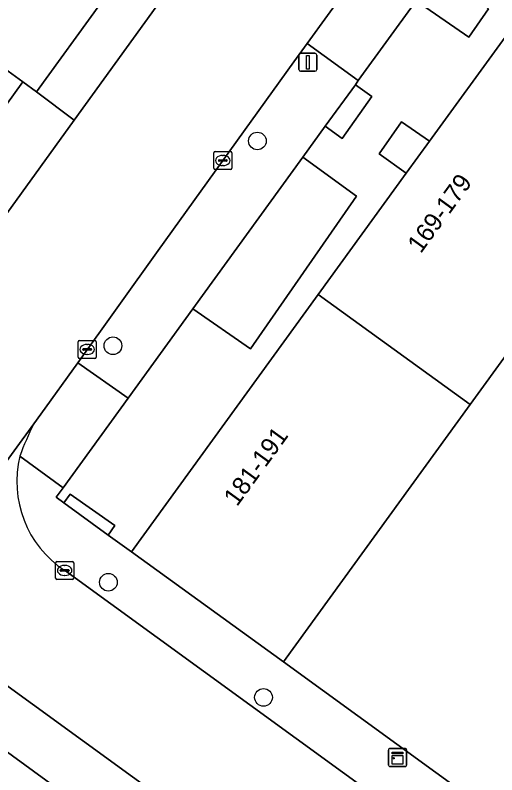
# Model space of a CAD drawing. Extents: x 159674 to 160531, y 382172 to 382904.
# Drawn here: x 160192.42 to 160219.05, y 382438.2 to 382480.25 of the extents above; entities that cross this region are included whole.
import ezdxf

# ---------------------------------------------------------------- set-up
doc = ezdxf.new("R2010")
doc.units = 0
for name, color, linetype in [('IMGEO_Boom', 7, 'Continuous'), ('IMGEO_Erf', 7, 'Continuous'), ('IMGEO_Groenvoorziening', 7, 'Continuous'), ('IMGEO_Kast', 7, 'Continuous'), ('IMGEO_Kolk', 7, 'Continuous'), ('IMGEO_Lichtmast', 7, 'Continuous'), ('IMGEO_Pand', 7, 'Continuous'), ('IMGEO_Pand_nummerreeks', 7, 'Continuous'), ('IMGEO_Rijbaan_lokaal_gesloten', 7, 'Continuous'), ('IMGEO_Rijbaan_lokaal_open', 7, 'Continuous'), ('IMGEO_Voetpad_open', 7, 'Continuous')]:
    doc.layers.add(name, color=color, linetype=linetype)

msp = doc.modelspace()

# ---------------------------------------------------------------- linework, layer by layer
at = {"layer": 'IMGEO_Boom'}
for centre in [(160205.813, 382473.283), (160197.829, 382461.949), (160197.574, 382448.859), (160206.154, 382442.486)]:
    msp.add_circle(centre, 0.489, dxfattribs=at)
at = {"layer": 'IMGEO_Erf'}
msp.add_lwpolyline([(160182.094, 382492.77), (160177.116, 382496.389), (160172.149, 382500), (160165.851, 382491.086), (160168.791, 382488.896), (160171.386, 382492.38), (160173.197, 382491.031), (160175.695, 382489.17), (160173.177, 382485.697), (160175.768, 382483.874), (160179.323, 382488.647), (160182.164, 382486.531), (160181.035, 382485.016), (160182.848, 382483.665), (160184.767, 382482.236), (160182.34, 382478.979), (160182.963, 382478.515), (160185.543, 382476.768), (160187.968, 382480.105), (160192.854, 382476.554), (160193.609, 382475.995), (160197.153, 382480.914)], dxfattribs=at)
at = {"layer": 'IMGEO_Groenvoorziening'}
msp.add_lwpolyline([(160254.885, 382500), (160239.266, 382511.108), (160237.217, 382512.565), (160235.158, 382509.653), (160239.464, 382506.53), (160240.092, 382507.396), (160248.493, 382501.304), (160247.547, 382500), (160238.256, 382487.19), (160227.923, 382472.943), (160217.589, 382458.696), (160207.256, 382444.449), (160248.967, 382414.122)], dxfattribs=at)
for points in [[(160215.757, 382482.642), (160214.787, 382481.302), (160214.604, 382481.05), (160217.516, 382479.035), (160218.591, 382480.589)], [(160211.235, 382476.399), (160209.566, 382474.095), (160210.502, 382473.418), (160212.151, 382475.752)], [(160215.333, 382473.267), (160213.776, 382474.343), (160212.558, 382472.581), (160214.05, 382471.498)], [(160208.327, 382472.386), (160202.241, 382463.985), (160205.436, 382461.77), (160211.301, 382470.232)], [(160195.105, 382453.261), (160197.564, 382451.474), (160197.933, 382451.998), (160195.455, 382453.742)]]:
    msp.add_lwpolyline(points, close=True, dxfattribs=at)
at = {"layer": 'IMGEO_Kast'}
for p, q in [((160213.143, 382439.656), (160213.984, 382439.656)), ((160213.984, 382439.656), (160213.143, 382439.656)), ((160213.068, 382438.731), (160213.068, 382439.572)), ((160213.068, 382439.572), (160213.068, 382438.731)), ((160214.068, 382439.581), (160214.068, 382438.74)), ((160214.068, 382438.74), (160214.068, 382439.581)), ((160213.993, 382438.656), (160213.152, 382438.656)), ((160213.152, 382438.656), (160213.993, 382438.656))]:
    msp.add_line(p, q, dxfattribs=at)
for points in [[(160213.263, 382439.446), (160213.863, 382439.446), (160213.863, 382439.361), (160213.263, 382439.361), (160213.263, 382439.446)], [(160213.263, 382439.271), (160213.863, 382439.271), (160213.863, 382438.782), (160213.263, 382438.782), (160213.263, 382439.271)]]:
    msp.add_lwpolyline(points, dxfattribs=at)
msp.add_circle((160213.347, 382439.12), 0.0377, dxfattribs=at)
for centre, start, end in [((160213.146, 382439.578), 92.4484, 184.2845), ((160213.146, 382439.578), 92.4484, 184.2845), ((160213.99, 382439.578), 2.4484, 94.2845), ((160213.99, 382439.578), 2.4484, 94.2845), ((160213.146, 382438.734), 182.4484, 274.2845), ((160213.146, 382438.734), 182.4484, 274.2845), ((160213.99, 382438.734), 272.4484, 4.2845), ((160213.99, 382438.734), 272.4484, 4.2845)]:
    msp.add_arc(centre, 0.0779, start, end, dxfattribs=at)
at = {"layer": 'IMGEO_Kolk'}
for p, q in [((160203.404, 382471.776), (160203.404, 382472.628)), ((160203.479, 382472.702), (160204.331, 382472.702)), ((160203.892, 382472.482), (160203.917, 382472.482)), ((160204.405, 382472.628), (160204.405, 382471.776)), ((160203.663, 382472.196), (160203.663, 382472.208)), ((160204.101, 382472.159), (160203.703, 382472.159)), ((160203.706, 382472.245), (160204.104, 382472.245)), ((160204.147, 382472.208), (160204.147, 382472.196)), ((160204.331, 382471.702), (160203.479, 382471.702)), ((160203.915, 382471.922), (160203.89, 382471.922)), ((160195.905, 382461.32), (160195.905, 382462.172)), ((160195.98, 382462.246), (160196.832, 382462.246)), ((160196.393, 382462.026), (160196.418, 382462.026)), ((160196.906, 382462.172), (160196.906, 382461.32)), ((160196.164, 382461.74), (160196.164, 382461.752)), ((160196.602, 382461.703), (160196.204, 382461.703)), ((160196.207, 382461.789), (160196.605, 382461.789)), ((160196.648, 382461.752), (160196.648, 382461.74)), ((160196.832, 382461.246), (160195.98, 382461.246)), ((160196.416, 382461.466), (160196.391, 382461.466)), ((160194.658, 382449.087), (160194.658, 382449.939)), ((160194.733, 382450.013), (160195.585, 382450.013)), ((160195.146, 382449.793), (160195.171, 382449.793)), ((160195.659, 382449.939), (160195.659, 382449.087)), ((160194.917, 382449.507), (160194.917, 382449.519)), ((160195.355, 382449.47), (160194.957, 382449.47)), ((160194.96, 382449.556), (160195.358, 382449.556)), ((160195.401, 382449.519), (160195.401, 382449.507)), ((160195.585, 382449.013), (160194.733, 382449.013)), ((160195.169, 382449.233), (160195.144, 382449.233))]:
    msp.add_line(p, q, dxfattribs=at)
for points in [[(160203.404, 382471.776), (160203.404, 382472.628)], [(160203.479, 382472.702), (160204.331, 382472.702)], [(160204.405, 382472.628), (160204.405, 382471.776)], [(160204.331, 382471.702), (160203.479, 382471.702)], [(160195.905, 382461.32), (160195.905, 382462.172)], [(160195.98, 382462.246), (160196.832, 382462.246)], [(160196.906, 382462.172), (160196.906, 382461.32)], [(160196.832, 382461.246), (160195.98, 382461.246)], [(160194.658, 382449.087), (160194.658, 382449.939)], [(160194.733, 382450.013), (160195.585, 382450.013)], [(160195.659, 382449.939), (160195.659, 382449.087)], [(160195.585, 382449.013), (160194.733, 382449.013)]]:
    msp.add_lwpolyline(points, dxfattribs=at)
for centre, radius, start, end in [((160203.481, 382472.626), 0.0765, 91.552, 178.448), ((160203.481, 382472.626), 0.0765, 91.552, 178.448), ((160204.329, 382472.626), 0.0765, 1.552, 88.448), ((160204.329, 382472.626), 0.0765, 1.552, 88.448), ((160203.703, 382472.205), 0.0403, 85.8775, 175.7526), ((160203.7, 382472.195), 0.0366, 178.938, 274.7102), ((160204.104, 382472.202), 0.043, 264.8664, 352.4533), ((160204.108, 382472.207), 0.0386, 1.7309, 96.639), ((160203.481, 382471.778), 0.0765, 181.552, 268.448), ((160203.481, 382471.778), 0.0765, 181.552, 268.448), ((160204.329, 382471.778), 0.0765, 271.552, 358.448), ((160204.329, 382471.778), 0.0765, 271.552, 358.448), ((160195.982, 382462.17), 0.0765, 91.552, 178.448), ((160195.982, 382462.17), 0.0765, 91.552, 178.448), ((160196.83, 382462.17), 0.0765, 1.552, 88.448), ((160196.83, 382462.17), 0.0765, 1.552, 88.448), ((160196.204, 382461.749), 0.0403, 85.8775, 175.7526), ((160196.201, 382461.739), 0.0366, 178.938, 274.7102), ((160196.605, 382461.746), 0.043, 264.8664, 352.4533), ((160196.609, 382461.751), 0.0386, 1.7309, 96.639), ((160195.982, 382461.322), 0.0765, 181.552, 268.448), ((160195.982, 382461.322), 0.0765, 181.552, 268.448), ((160196.83, 382461.322), 0.0765, 271.552, 358.448), ((160196.83, 382461.322), 0.0765, 271.552, 358.448), ((160194.735, 382449.937), 0.0765, 91.552, 178.448), ((160194.735, 382449.937), 0.0765, 91.552, 178.448), ((160195.583, 382449.937), 0.0765, 1.552, 88.448), ((160195.583, 382449.937), 0.0765, 1.552, 88.448), ((160194.957, 382449.516), 0.0403, 85.8775, 175.7526), ((160194.954, 382449.506), 0.0366, 178.938, 274.7102), ((160195.358, 382449.513), 0.043, 264.8664, 352.4533), ((160195.362, 382449.518), 0.0386, 1.7309, 96.639), ((160194.735, 382449.089), 0.0765, 181.552, 268.448), ((160194.735, 382449.089), 0.0765, 181.552, 268.448), ((160195.583, 382449.089), 0.0765, 271.552, 358.448), ((160195.583, 382449.089), 0.0765, 271.552, 358.448)]:
    msp.add_arc(centre, radius, start, end, dxfattribs=at)
for centre, major_axis, ratio, start_param, end_param in [((160203.891, 382472.202), (-0.387, 0.002), 0.722429, 4.712389, 7.853982), ((160203.916, 382472.202), (-0.39, 0.002), 0.717154, 1.570796, 4.712389), ((160196.392, 382461.746), (-0.387, 0.002), 0.722429, 4.712389, 7.853982), ((160196.417, 382461.746), (-0.39, 0.002), 0.717154, 1.570796, 4.712389), ((160195.145, 382449.513), (-0.387, 0.002), 0.722429, 4.712389, 7.853982), ((160195.17, 382449.513), (-0.39, 0.002), 0.717154, 1.570796, 4.712389)]:
    msp.add_ellipse(centre, major_axis=major_axis, ratio=ratio, start_param=start_param, end_param=end_param, dxfattribs=at)
at = {"layer": 'IMGEO_Lichtmast'}
for p, q in [((160208.108, 382477.241), (160208.108, 382478.041)), ((160208.108, 382478.041), (160208.108, 382477.241)), ((160208.208, 382478.141), (160208.998, 382478.141)), ((160208.998, 382478.141), (160208.208, 382478.141)), ((160209.098, 382478.041), (160209.098, 382477.241)), ((160209.098, 382477.241), (160209.098, 382478.041)), ((160208.998, 382477.141), (160208.208, 382477.141)), ((160208.208, 382477.141), (160208.998, 382477.141))]:
    msp.add_line(p, q, dxfattribs=at)
msp.add_lwpolyline([(160208.528, 382478.016), (160208.678, 382478.016), (160208.678, 382477.266), (160208.528, 382477.266), (160208.528, 382478.016)], dxfattribs=at)
for centre, start, end in [((160208.208, 382478.041), 90, 180), ((160208.208, 382478.041), 90, 180), ((160208.998, 382478.041), 0, 90), ((160208.998, 382478.041), 360, 90), ((160208.208, 382477.241), 180, 270), ((160208.208, 382477.241), 180, 270), ((160208.998, 382477.241), 270, 0), ((160208.998, 382477.241), 270, 0)]:
    msp.add_arc(centre, 0.1, start, end, dxfattribs=at)
at = {"layer": 'IMGEO_Pand'}
for points in [[(160192.854, 382476.554), (160187.968, 382480.105), (160185.543, 382476.768), (160190.429, 382473.217)], [(160227.923, 382472.943), (160219.517, 382479.034), (160215.333, 382473.267), (160214.05, 382471.498), (160209.182, 382464.788), (160217.589, 382458.696)], [(160217.589, 382458.696), (160209.182, 382464.788), (160198.847, 382450.542), (160207.256, 382444.449)]]:
    msp.add_lwpolyline(points, close=True, dxfattribs=at)
at = {"layer": 'IMGEO_Rijbaan_lokaal_gesloten'}
for points in [[(160315.311, 382639.622), (160304.717, 382625.008), (160302.639, 382622.143), (160290.62, 382605.563), (160279.709, 382590.612), (160279.414, 382590.208), (160269.482, 382576.534), (160263.507, 382568.309), (160253.466, 382554.485), (160253.079, 382553.951), (160242.339, 382539.119), (160232.376, 382525.365), (160226.58, 382517.362), (160218.061, 382505.6), (160216.652, 382503.655), (160216.208, 382503.063), (160216.121, 382502.946), (160214.024, 382500), (160205.773, 382488.409), (160195.682, 382474.429), (160187.988, 382463.77), (160179.328, 382451.773), (160168.227, 382436.541)], [(160176.58, 382434.549), (160182.656, 382442.82), (160193.454, 382457.632), (160193.845, 382458.168), (160195.88, 382461.012), (160200.33, 382467.23), (160207.829, 382477.658), (160208.563, 382478.674), (160211.935, 382483.338), (160213.016, 382484.835), (160216.503, 382489.659), (160218.852, 382492.909), (160223.908, 382500), (160224.532, 382500.867), (160228.891, 382506.926), (160232.328, 382511.703), (160235.142, 382515.615), (160244.516, 382528.409), (160246.675, 382531.388), (160247.218, 382532.137), (160249.155, 382534.809), (160256.944, 382545.554)]]:
    msp.add_lwpolyline(points, dxfattribs=at)
at = {"layer": 'IMGEO_Rijbaan_lokaal_open'}
for points in [[(160193.454, 382457.632), (160182.656, 382442.82)], [(160246.396, 382412.259), (160195.141, 382449.525)], [(160190.801, 382443.973), (160201.47, 382436.234), (160206.885, 382432.306), (160209.493, 382430.414), (160215.878, 382425.783), (160221.062, 382422.022), (160225.848, 382418.551), (160228.002, 382418.705)]]:
    msp.add_lwpolyline(points, dxfattribs=at)
for centre, radius, start, end in [((160208.335, 382450.15), 16.656, 153.3079, 160.0251), ((160198.401, 382454.431), 5.891, 166.1659, 236.4008)]:
    msp.add_arc(centre, radius, start, end, dxfattribs=at)
at = {"layer": 'IMGEO_Voetpad_open'}
for points in [[(160197.153, 382480.914), (160193.609, 382475.995), (160195.682, 382474.429), (160205.773, 382488.409)], [(160218.591, 382480.589), (160217.516, 382479.035), (160214.604, 382481.05), (160211.397, 382476.623), (160211.235, 382476.399), (160212.151, 382475.752), (160210.502, 382473.418), (160209.566, 382474.095), (160208.327, 382472.386), (160211.301, 382470.232), (160205.436, 382461.77), (160202.241, 382463.985), (160198.668, 382459.054), (160195.07, 382454.089), (160194.689, 382453.563), (160195.105, 382453.261), (160195.455, 382453.742), (160197.933, 382451.998), (160197.564, 382451.474), (160198.847, 382450.542), (160209.182, 382464.788), (160214.05, 382471.498), (160212.558, 382472.581), (160213.776, 382474.343), (160215.333, 382473.267), (160219.517, 382479.034)], [(160192.681, 382455.84), (160195.07, 382454.089), (160198.668, 382459.054), (160195.88, 382461.012), (160193.845, 382458.168), (160193.454, 382457.632)], [(160207.256, 382444.449), (160198.847, 382450.542), (160197.564, 382451.474), (160195.105, 382453.261), (160194.689, 382453.563), (160195.07, 382454.089), (160192.681, 382455.84)], [(160195.141, 382449.525), (160246.396, 382412.259), (160248.967, 382414.122), (160207.256, 382444.449)], [(160189.455, 382441.296), (160199.721, 382433.813), (160201.47, 382436.234), (160190.801, 382443.973)]]:
    msp.add_lwpolyline(points, dxfattribs=at)
for points in [[(160214.604, 382481.05), (160214.787, 382481.302), (160211.935, 382483.338), (160208.563, 382478.674), (160211.397, 382476.623)], [(160208.327, 382472.386), (160209.566, 382474.095), (160211.235, 382476.399), (160211.397, 382476.623), (160208.563, 382478.674), (160207.829, 382477.658), (160200.33, 382467.23), (160195.88, 382461.012), (160198.668, 382459.054), (160202.241, 382463.985)], [(160193.609, 382475.995), (160192.854, 382476.554), (160190.429, 382473.217), (160190.085, 382472.747), (160191.984, 382471.373), (160187.039, 382464.471), (160187.988, 382463.77), (160195.682, 382474.429)], [(160189.255, 382436.517), (160203.478, 382426.15), (160217.701, 382415.783), (160231.923, 382405.417), (160233.442, 382409.235), (160228.331, 382412.96), (160219.275, 382419.561), (160214.103, 382423.331), (160205.134, 382429.868), (160199.721, 382433.813), (160189.455, 382441.296)]]:
    msp.add_lwpolyline(points, close=True, dxfattribs=at)
for centre, radius, start, end in [((160208.335, 382450.15), 16.656, 153.3079, 160.0251), ((160198.401, 382454.431), 5.891, 166.1659, 236.4008)]:
    msp.add_arc(centre, radius, start, end, dxfattribs=at)

# ---------------------------------------------------------------- texts
at = {"layer": 'IMGEO_Pand_nummerreeks'}
for s, rotation, p in [('169-179', 54.0414, (160214.849, 382467.014)), ('181-191', 54.0405, (160204.688, 382453.008))]:
    msp.add_text(s, height=1, rotation=rotation, dxfattribs=at).set_placement(p)

doc.saveas('drawing.dxf')
